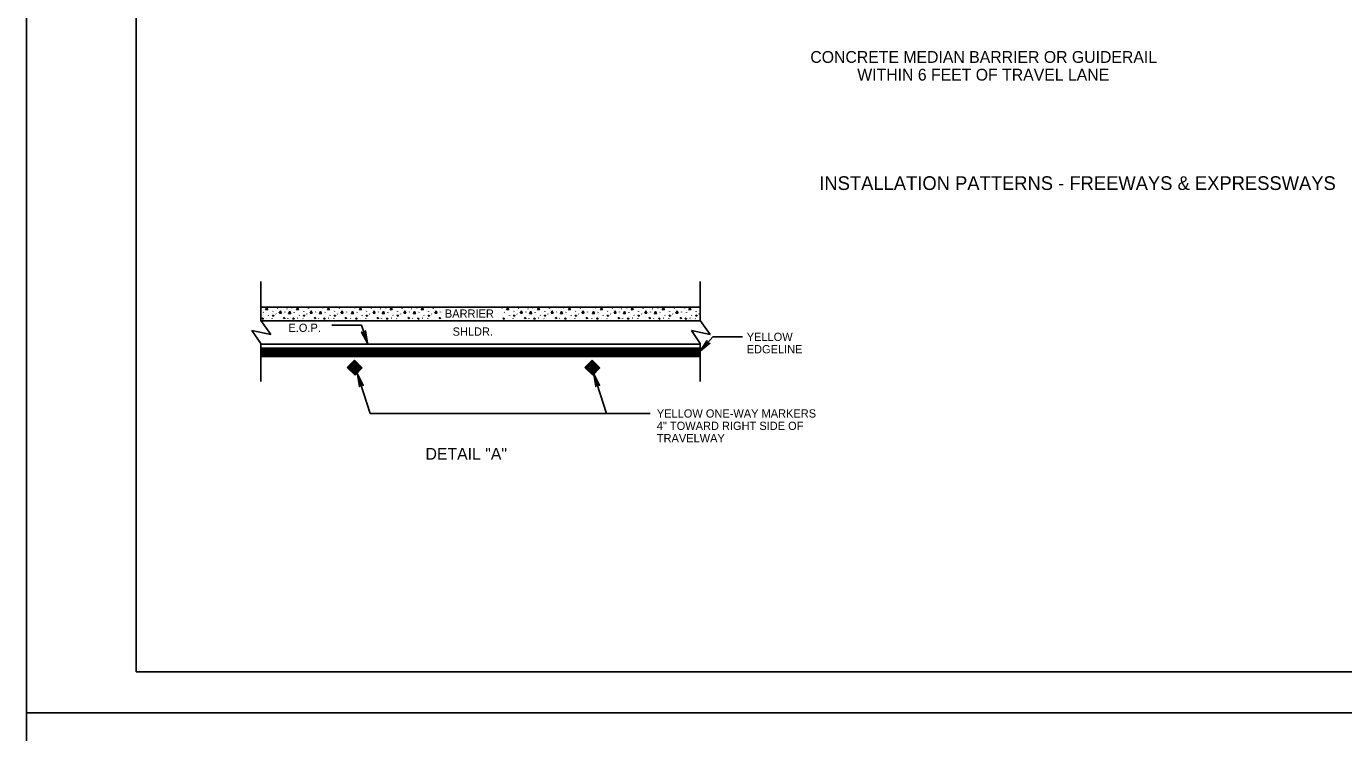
# Model space of a CAD drawing. Extents: x 639362 to 641108, y 298458 to 299646.
# Drawn here: x 639362.3 to 639841.8, y 299044.4 to 299301.7 of the extents above; entities that cross this region are included whole.
import ezdxf

# ---------------------------------------------------------------- set-up
doc = ezdxf.new("R2010")
doc.units = 0
for name, color, linetype in [('1', 7, 'Continuous'), ('2', 7, 'Continuous'), ('PLT-BNDY', 7, 'Continuous')]:
    doc.layers.add(name, color=color, linetype=linetype)

msp = doc.modelspace()

# ---------------------------------------------------------------- linework, layer by layer
at = {"layer": '1'}
for p, q in [((639402.31, 299630.63), (639402.31, 299066.63)), ((640188.31, 299066.63), (639402.31, 299066.63)), ((639402.31, 299066.63), (639988.31, 299066.63))]:
    msp.add_line(p, q, dxfattribs=at)
at = {"layer": '2'}
for p, q in [((639447.61, 299208.8), (639447.61, 299194.59)), ((639607.62, 299208.8), (639607.62, 299194.59)), ((639447.61, 299199.41), (639607.62, 299199.41)), ((639447.77, 299199.17), (639447.84, 299199.08)), ((639448.55, 299197.43), (639448.61, 299197.56)), ((639449.79, 299195.44), (639449.85, 299195.35)), ((639450.39, 299196.48), (639450.45, 299196.39)), ((639451.77, 299195.27), (639451.83, 299195.18)), ((639452.05, 299197.76), (639452.11, 299197.9)), ((639453.16, 299196.95), (639453.22, 299196.86)), ((639453.74, 299199.02), (639453.8, 299198.93)), ((639456.26, 299199.25), (639456.32, 299199.15)), ((639456.38, 299197.61), (639456.44, 299197.75)), ((639457.13, 299198.83), (639457.19, 299198.74)), ((639457.47, 299195.36), (639457.53, 299195.27)), ((639459, 299199.17), (639459.06, 299199.08)), ((639459.78, 299197.43), (639459.83, 299197.56)), ((639461.01, 299195.44), (639461.07, 299195.35)), ((639461.61, 299196.48), (639461.68, 299196.39)), ((639463, 299195.27), (639463.06, 299195.18)), ((639463.27, 299197.76), (639463.33, 299197.9)), ((639464.38, 299196.95), (639464.44, 299196.86)), ((639464.96, 299199.02), (639465.02, 299198.93)), ((639467.48, 299199.25), (639467.54, 299199.15)), ((639467.6, 299197.61), (639467.66, 299197.75)), ((639468.35, 299198.83), (639468.41, 299198.74)), ((639468.69, 299195.36), (639468.76, 299195.27)), ((639470.22, 299199.17), (639470.29, 299199.08)), ((639471, 299197.43), (639471.06, 299197.56)), ((639472.23, 299195.44), (639472.3, 299195.35)), ((639472.84, 299196.48), (639472.9, 299196.39)), ((639474.22, 299195.27), (639474.28, 299195.18)), ((639474.5, 299197.76), (639474.55, 299197.9)), ((639475.61, 299196.95), (639475.67, 299196.86)), ((639476.19, 299199.02), (639476.25, 299198.93)), ((639478.71, 299199.25), (639478.77, 299199.15)), ((639478.83, 299197.61), (639478.89, 299197.75)), ((639480.01, 299198.83), (639480.07, 299198.74)), ((639480.35, 299195.36), (639480.41, 299195.27)), ((639481.88, 299199.17), (639481.94, 299199.08)), ((639482.66, 299197.43), (639482.71, 299197.56)), ((639483.89, 299195.44), (639483.95, 299195.35)), ((639484.5, 299196.48), (639484.56, 299196.39)), ((639485.88, 299195.27), (639485.94, 299195.18)), ((639486.16, 299197.76), (639486.21, 299197.9)), ((639487.26, 299196.95), (639487.33, 299196.86)), ((639487.84, 299199.02), (639487.9, 299198.93)), ((639490.36, 299199.25), (639490.42, 299199.15)), ((639490.49, 299197.61), (639490.54, 299197.75)), ((639491.23, 299198.83), (639491.29, 299198.74)), ((639491.58, 299195.36), (639491.64, 299195.27)), ((639493.1, 299199.17), (639493.17, 299199.08)), ((639493.88, 299197.43), (639493.94, 299197.56)), ((639495.12, 299195.44), (639495.18, 299195.35)), ((639495.72, 299196.48), (639495.78, 299196.39)), ((639497.1, 299195.27), (639497.16, 299195.18)), ((639497.38, 299197.76), (639497.44, 299197.9)), ((639498.49, 299196.95), (639498.55, 299196.86)), ((639499.07, 299199.02), (639499.13, 299198.93)), ((639501.59, 299199.25), (639501.65, 299199.15)), ((639501.71, 299197.61), (639501.77, 299197.75)), ((639502.54, 299198.83), (639502.6, 299198.74)), ((639502.89, 299195.36), (639502.95, 299195.27)), ((639504.42, 299199.17), (639504.48, 299199.08)), ((639505.19, 299197.43), (639505.25, 299197.56)), ((639506.43, 299195.44), (639506.49, 299195.35)), ((639507.03, 299196.48), (639507.09, 299196.39)), ((639508.41, 299195.27), (639508.47, 299195.18)), ((639508.69, 299197.76), (639508.75, 299197.9)), ((639509.8, 299196.95), (639509.86, 299196.86)), ((639510.38, 299199.02), (639510.44, 299198.93)), ((639512.9, 299199.25), (639512.96, 299199.15)), ((639513.02, 299197.61), (639513.08, 299197.75)), ((639535.5, 299199.17), (639535.56, 299199.08)), ((639536.28, 299197.43), (639536.33, 299197.56)), ((639537.51, 299195.44), (639537.57, 299195.35)), ((639538.12, 299196.48), (639538.18, 299196.39)), ((639539.5, 299195.27), (639539.56, 299195.18)), ((639539.78, 299197.76), (639539.83, 299197.9)), ((639540.88, 299196.95), (639540.95, 299196.86)), ((639541.46, 299199.02), (639541.52, 299198.93)), ((639543.98, 299199.25), (639544.04, 299199.15)), ((639544.11, 299197.61), (639544.16, 299197.75)), ((639544.85, 299198.83), (639544.91, 299198.74)), ((639545.2, 299195.36), (639545.26, 299195.27)), ((639546.72, 299199.17), (639546.79, 299199.08)), ((639547.5, 299197.43), (639547.56, 299197.56)), ((639548.74, 299195.44), (639548.8, 299195.35)), ((639549.34, 299196.48), (639549.4, 299196.39)), ((639550.72, 299195.27), (639550.78, 299195.18)), ((639551, 299197.76), (639551.06, 299197.9)), ((639552.11, 299196.95), (639552.17, 299196.86)), ((639552.69, 299199.02), (639552.75, 299198.93)), ((639555.21, 299199.25), (639555.27, 299199.15)), ((639555.33, 299197.61), (639555.39, 299197.75)), ((639556.08, 299198.83), (639556.14, 299198.74)), ((639556.42, 299195.36), (639556.48, 299195.27)), ((639557.95, 299199.17), (639558.01, 299199.08)), ((639558.73, 299197.43), (639558.78, 299197.56)), ((639559.96, 299195.44), (639560.02, 299195.35)), ((639560.57, 299196.48), (639560.63, 299196.39)), ((639561.95, 299195.27), (639562.01, 299195.18)), ((639562.22, 299197.76), (639562.28, 299197.9)), ((639563.33, 299196.95), (639563.39, 299196.86)), ((639563.91, 299199.02), (639563.97, 299198.93)), ((639566.43, 299199.25), (639566.49, 299199.15)), ((639566.56, 299197.61), (639566.61, 299197.75)), ((639567.73, 299198.83), (639567.79, 299198.74)), ((639568.08, 299195.36), (639568.14, 299195.27)), ((639569.61, 299199.17), (639569.67, 299199.08)), ((639570.38, 299197.43), (639570.44, 299197.56)), ((639571.62, 299195.44), (639571.68, 299195.35)), ((639572.22, 299196.48), (639572.28, 299196.39)), ((639573.6, 299195.27), (639573.67, 299195.18)), ((639573.88, 299197.76), (639573.94, 299197.9)), ((639574.99, 299196.95), (639575.05, 299196.86)), ((639575.57, 299199.02), (639575.63, 299198.93)), ((639578.09, 299199.25), (639578.15, 299199.15)), ((639578.21, 299197.61), (639578.27, 299197.75)), ((639578.96, 299198.83), (639579.02, 299198.74)), ((639579.3, 299195.36), (639579.36, 299195.27)), ((639580.83, 299199.17), (639580.89, 299199.08)), ((639581.61, 299197.43), (639581.66, 299197.56)), ((639582.84, 299195.44), (639582.9, 299195.35)), ((639583.45, 299196.48), (639583.51, 299196.39)), ((639584.83, 299195.27), (639584.89, 299195.18)), ((639585.11, 299197.76), (639585.16, 299197.9)), ((639586.21, 299196.95), (639586.28, 299196.86)), ((639586.79, 299199.02), (639586.86, 299198.93)), ((639589.31, 299199.25), (639589.38, 299199.15)), ((639589.44, 299197.61), (639589.49, 299197.75)), ((639590.27, 299198.83), (639590.33, 299198.74)), ((639590.61, 299195.36), (639590.68, 299195.27)), ((639592.14, 299199.17), (639592.2, 299199.08)), ((639592.92, 299197.43), (639592.97, 299197.56)), ((639594.15, 299195.44), (639594.22, 299195.35)), ((639594.76, 299196.48), (639594.82, 299196.39)), ((639596.14, 299195.27), (639596.2, 299195.18)), ((639596.42, 299197.76), (639596.47, 299197.9)), ((639597.53, 299196.95), (639597.59, 299196.86)), ((639598.1, 299199.02), (639598.17, 299198.93)), ((639600.62, 299199.25), (639600.69, 299199.15)), ((639600.75, 299197.61), (639600.8, 299197.75)), ((639601.81, 299199.17), (639601.87, 299199.08)), ((639602.59, 299197.43), (639602.65, 299197.56)), ((639603.82, 299195.44), (639603.89, 299195.35)), ((639604.43, 299196.48), (639604.49, 299196.39)), ((639605.81, 299195.27), (639605.87, 299195.18)), ((639606.09, 299197.76), (639606.14, 299197.9)), ((639607.2, 299196.95), (639607.26, 299196.86)), ((639447.61, 299186.11), (639444.43, 299190.88)), ((639444.43, 299190.88), (639451.26, 299189.48)), ((639451.26, 299189.48), (639447.61, 299194.59)), ((639447.61, 299194.41), (639607.62, 299194.41)), ((639453.99, 299194.47), (639454.05, 299194.6)), ((639465.21, 299194.47), (639465.27, 299194.6)), ((639473.46, 299192.9), (639484.32, 299192.9)), ((639476.44, 299194.47), (639476.5, 299194.6)), ((639486.44, 299186.25), (639484.32, 299192.9)), ((639488.1, 299194.47), (639488.15, 299194.6)), ((639499.32, 299194.47), (639499.38, 299194.6)), ((639510.63, 299194.47), (639510.69, 299194.6)), ((639541.72, 299194.47), (639541.77, 299194.6)), ((639552.94, 299194.47), (639553, 299194.6)), ((639564.17, 299194.47), (639564.22, 299194.6)), ((639575.82, 299194.47), (639575.88, 299194.6)), ((639587.05, 299194.47), (639587.1, 299194.6)), ((639598.36, 299194.47), (639598.41, 299194.6)), ((639607.62, 299186.11), (639604.44, 299190.88)), ((639604.44, 299190.88), (639611.26, 299189.48)), ((639611.26, 299189.48), (639607.62, 299194.59)), ((639447.61, 299186.11), (639447.61, 299172.29)), ((639447.61, 299185.91), (639607.62, 299185.91)), ((639607.54, 299183.32), (639612.16, 299188.55)), ((639607.62, 299186.11), (639607.62, 299172.29)), ((639623.02, 299188.55), (639612.16, 299188.55)), ((639447.61, 299184.41), (639607.62, 299184.41)), ((639447.61, 299184.41), (639607.62, 299184.41)), ((639447.61, 299184.41), (639607.62, 299184.41)), ((639447.61, 299184.11), (639607.62, 299184.11)), ((639447.61, 299183.81), (639607.62, 299183.81)), ((639447.61, 299183.51), (639607.62, 299183.51)), ((639447.61, 299183.21), (639607.62, 299183.21)), ((639447.61, 299182.91), (639607.62, 299182.91)), ((639447.61, 299182.61), (639607.62, 299182.61)), ((639447.61, 299182.31), (639607.62, 299182.31)), ((639447.61, 299182.01), (639607.62, 299182.01)), ((639447.61, 299181.71), (639607.62, 299181.71)), ((639447.61, 299181.41), (639607.62, 299181.41)), ((639479.12, 299177.45), (639481.78, 299180.1)), ((639481.94, 299174.64), (639479.12, 299177.45)), ((639479.46, 299177.51), (639481.72, 299179.76)), ((639482, 299174.97), (639479.46, 299177.51)), ((639479.84, 299177.51), (639481.72, 299179.39)), ((639482, 299175.35), (639479.84, 299177.51)), ((639480.22, 299177.51), (639481.72, 299179.01)), ((639482, 299175.72), (639480.22, 299177.51)), ((639480.59, 299177.51), (639481.72, 299178.64)), ((639482, 299176.1), (639480.59, 299177.51)), ((639480.97, 299177.51), (639481.72, 299178.26)), ((639482, 299176.47), (639480.97, 299177.51)), ((639481.34, 299177.51), (639481.72, 299177.89)), ((639482, 299176.85), (639481.34, 299177.51)), ((639481.72, 299179.76), (639484.26, 299177.22)), ((639481.72, 299179.39), (639483.88, 299177.23)), ((639481.72, 299179.01), (639483.51, 299177.23)), ((639481.72, 299178.64), (639483.13, 299177.23)), ((639481.72, 299178.26), (639482.75, 299177.23)), ((639481.72, 299177.89), (639482.38, 299177.23)), ((639481.72, 299177.51), (639482, 299177.22)), ((639481.78, 299180.1), (639484.59, 299177.29)), ((639484.59, 299177.29), (639481.94, 299174.64)), ((639483.88, 299177.23), (639482, 299175.35)), ((639483.51, 299177.23), (639482, 299175.72)), ((639483.13, 299177.23), (639482, 299176.1)), ((639482.75, 299177.23), (639482, 299176.47)), ((639482.38, 299177.23), (639482, 299176.85)), ((639484.26, 299177.22), (639482, 299174.97)), ((639565.63, 299177.45), (639568.28, 299180.1)), ((639568.45, 299174.64), (639565.63, 299177.45)), ((639565.97, 299177.51), (639568.23, 299179.76)), ((639568.51, 299174.97), (639565.97, 299177.51)), ((639566.35, 299177.51), (639568.23, 299179.39)), ((639568.51, 299175.35), (639566.35, 299177.51)), ((639566.72, 299177.51), (639568.23, 299179.01)), ((639568.51, 299175.72), (639566.72, 299177.51)), ((639567.1, 299177.51), (639568.23, 299178.64)), ((639568.51, 299176.1), (639567.1, 299177.51)), ((639567.48, 299177.51), (639568.23, 299178.26)), ((639568.51, 299176.47), (639567.48, 299177.51)), ((639567.85, 299177.51), (639568.23, 299177.89)), ((639568.51, 299176.85), (639567.85, 299177.51)), ((639568.22, 299177.51), (639568.51, 299177.22)), ((639568.23, 299179.76), (639570.77, 299177.22)), ((639568.23, 299179.39), (639570.39, 299177.23)), ((639568.23, 299179.01), (639570.02, 299177.23)), ((639568.23, 299178.64), (639569.64, 299177.23)), ((639568.23, 299178.26), (639569.26, 299177.23)), ((639568.23, 299177.89), (639568.89, 299177.23)), ((639568.28, 299180.1), (639571.1, 299177.29)), ((639571.1, 299177.29), (639568.45, 299174.64)), ((639570.39, 299177.23), (639568.51, 299175.35)), ((639570.02, 299177.23), (639568.51, 299175.72)), ((639569.64, 299177.23), (639568.51, 299176.1)), ((639569.26, 299177.23), (639568.51, 299176.47)), ((639568.89, 299177.23), (639568.51, 299176.85)), ((639570.77, 299177.22), (639568.51, 299174.97)), ((639482.85, 299175.04), (639487.43, 299160.68)), ((639568.85, 299175.04), (639573.43, 299160.68)), ((639589.34, 299160.68), (639487.43, 299160.68))]:
    msp.add_line(p, q, dxfattribs=at)
msp.add_lwpolyline([(639447.61, 299194.41), (639607.62, 299194.41), (639607.62, 299199.41), (639447.61, 299199.41)], close=True, dxfattribs=at)
for points in [[(639448.11, 299195.04), (639448.28, 299195.41), (639448.58, 299195.19), (639448.11, 299195.04)], [(639449.42, 299198.44), (639449.82, 299199.19), (639450.13, 299198.5), (639449.43, 299198.44)], [(639451.94, 299196.1), (639452.12, 299196.46), (639452.41, 299196.25), (639451.94, 299196.1)], [(639454.38, 299197.22), (639454.78, 299197.97), (639455.1, 299197.27), (639454.4, 299197.22)], [(639455.94, 299195.23), (639456.12, 299195.6), (639456.41, 299195.38), (639455.94, 299195.23)], [(639457.78, 299197.03), (639458.18, 299197.78), (639458.49, 299197.09), (639457.79, 299197.03)], [(639459.33, 299195.04), (639459.51, 299195.41), (639459.8, 299195.19), (639459.33, 299195.04)], [(639460.64, 299198.44), (639461.04, 299199.19), (639461.35, 299198.5), (639460.66, 299198.44)], [(639463.17, 299196.1), (639463.35, 299196.46), (639463.64, 299196.25), (639463.17, 299196.1)], [(639465.61, 299197.22), (639466.01, 299197.97), (639466.32, 299197.27), (639465.62, 299197.22)], [(639467.17, 299195.23), (639467.34, 299195.6), (639467.64, 299195.38), (639467.17, 299195.23)], [(639469, 299197.03), (639469.4, 299197.78), (639469.71, 299197.09), (639469.01, 299197.03)], [(639470.56, 299195.04), (639470.73, 299195.41), (639471.03, 299195.19), (639470.56, 299195.04)], [(639471.87, 299198.44), (639472.27, 299199.19), (639472.57, 299198.5), (639471.88, 299198.44)], [(639474.39, 299196.1), (639474.57, 299196.46), (639474.86, 299196.25), (639474.39, 299196.1)], [(639476.83, 299197.22), (639477.23, 299197.97), (639477.55, 299197.27), (639476.85, 299197.22)], [(639478.39, 299195.23), (639478.57, 299195.6), (639478.86, 299195.38), (639478.39, 299195.23)], [(639480.66, 299197.03), (639481.06, 299197.78), (639481.37, 299197.09), (639480.67, 299197.03)], [(639482.21, 299195.04), (639482.39, 299195.41), (639482.68, 299195.19), (639482.21, 299195.04)], [(639483.52, 299198.44), (639483.92, 299199.19), (639484.23, 299198.5), (639483.54, 299198.44)], [(639486.05, 299196.1), (639486.23, 299196.46), (639486.52, 299196.25), (639486.05, 299196.1)], [(639488.49, 299197.22), (639488.89, 299197.97), (639489.2, 299197.27), (639488.51, 299197.22)], [(639490.05, 299195.23), (639490.22, 299195.6), (639490.52, 299195.38), (639490.05, 299195.23)], [(639491.88, 299197.03), (639492.28, 299197.78), (639492.59, 299197.09), (639491.9, 299197.03)], [(639493.44, 299195.04), (639493.61, 299195.41), (639493.91, 299195.19), (639493.44, 299195.04)], [(639494.75, 299198.44), (639495.15, 299199.19), (639495.46, 299198.5), (639494.76, 299198.44)], [(639497.27, 299196.1), (639497.45, 299196.46), (639497.75, 299196.25), (639497.27, 299196.1)], [(639499.71, 299197.22), (639500.11, 299197.97), (639500.43, 299197.27), (639499.73, 299197.22)], [(639501.27, 299195.23), (639501.45, 299195.6), (639501.74, 299195.38), (639501.27, 299195.23)], [(639503.2, 299197.03), (639503.59, 299197.78), (639503.9, 299197.09), (639503.21, 299197.03)], [(639504.75, 299195.04), (639504.92, 299195.41), (639505.22, 299195.19), (639504.75, 299195.04)], [(639506.06, 299198.44), (639506.46, 299199.19), (639506.77, 299198.5), (639506.08, 299198.44)], [(639508.58, 299196.1), (639508.76, 299196.46), (639509.06, 299196.25), (639508.58, 299196.1)], [(639511.03, 299197.22), (639511.42, 299197.97), (639511.74, 299197.27), (639511.04, 299197.22)], [(639512.58, 299195.23), (639512.76, 299195.6), (639513.06, 299195.38), (639512.58, 299195.23)], [(639535.83, 299195.04), (639536.01, 299195.41), (639536.3, 299195.19), (639535.83, 299195.04)], [(639537.14, 299198.44), (639537.54, 299199.19), (639537.85, 299198.5), (639537.16, 299198.44)], [(639539.67, 299196.1), (639539.85, 299196.46), (639540.14, 299196.25), (639539.67, 299196.1)], [(639542.11, 299197.22), (639542.51, 299197.97), (639542.82, 299197.27), (639542.13, 299197.22)], [(639543.67, 299195.23), (639543.84, 299195.6), (639544.14, 299195.38), (639543.67, 299195.23)], [(639545.5, 299197.03), (639545.9, 299197.78), (639546.21, 299197.09), (639545.52, 299197.03)], [(639547.06, 299195.04), (639547.23, 299195.41), (639547.53, 299195.19), (639547.06, 299195.04)], [(639548.37, 299198.44), (639548.77, 299199.19), (639549.08, 299198.5), (639548.38, 299198.44)], [(639550.89, 299196.1), (639551.07, 299196.46), (639551.37, 299196.25), (639550.89, 299196.1)], [(639553.33, 299197.22), (639553.73, 299197.97), (639554.05, 299197.27), (639553.35, 299197.22)], [(639554.89, 299195.23), (639555.07, 299195.6), (639555.36, 299195.38), (639554.89, 299195.23)], [(639556.73, 299197.03), (639557.13, 299197.78), (639557.44, 299197.09), (639556.74, 299197.03)], [(639558.28, 299195.04), (639558.46, 299195.41), (639558.75, 299195.19), (639558.28, 299195.04)], [(639559.59, 299198.44), (639559.99, 299199.19), (639560.3, 299198.5), (639559.61, 299198.44)], [(639562.12, 299196.1), (639562.3, 299196.46), (639562.59, 299196.25), (639562.12, 299196.1)], [(639564.56, 299197.22), (639564.96, 299197.97), (639565.27, 299197.27), (639564.58, 299197.22)], [(639566.12, 299195.23), (639566.29, 299195.6), (639566.59, 299195.38), (639566.12, 299195.23)], [(639568.39, 299197.03), (639568.78, 299197.78), (639569.09, 299197.09), (639568.4, 299197.03)], [(639569.94, 299195.04), (639570.11, 299195.41), (639570.41, 299195.19), (639569.94, 299195.04)], [(639571.25, 299198.44), (639571.65, 299199.19), (639571.96, 299198.5), (639571.27, 299198.44)], [(639573.77, 299196.1), (639573.95, 299196.46), (639574.25, 299196.25), (639573.77, 299196.1)], [(639576.22, 299197.22), (639576.61, 299197.97), (639576.93, 299197.27), (639576.23, 299197.22)], [(639577.77, 299195.23), (639577.95, 299195.6), (639578.25, 299195.38), (639577.77, 299195.23)], [(639579.61, 299197.03), (639580.01, 299197.78), (639580.32, 299197.09), (639579.62, 299197.03)], [(639581.16, 299195.04), (639581.34, 299195.41), (639581.64, 299195.19), (639581.16, 299195.04)], [(639582.47, 299198.44), (639582.87, 299199.19), (639583.18, 299198.5), (639582.49, 299198.44)], [(639585, 299196.1), (639585.18, 299196.46), (639585.47, 299196.25), (639585, 299196.1)], [(639587.44, 299197.22), (639587.84, 299197.97), (639588.15, 299197.27), (639587.46, 299197.22)], [(639589, 299195.23), (639589.17, 299195.6), (639589.47, 299195.38), (639589, 299195.23)], [(639590.92, 299197.03), (639591.32, 299197.78), (639591.63, 299197.09), (639590.93, 299197.03)], [(639592.47, 299195.04), (639592.65, 299195.41), (639592.95, 299195.19), (639592.47, 299195.04)], [(639593.78, 299198.44), (639594.18, 299199.19), (639594.49, 299198.5), (639593.8, 299198.44)], [(639596.31, 299196.1), (639596.49, 299196.46), (639596.78, 299196.25), (639596.31, 299196.1)], [(639598.75, 299197.22), (639599.15, 299197.97), (639599.47, 299197.27), (639598.77, 299197.22)], [(639600.31, 299195.23), (639600.48, 299195.6), (639600.78, 299195.38), (639600.31, 299195.23)], [(639602.14, 299195.04), (639602.32, 299195.41), (639602.62, 299195.19), (639602.14, 299195.04)], [(639603.46, 299198.44), (639603.85, 299199.19), (639604.16, 299198.5), (639603.47, 299198.44)], [(639605.98, 299196.1), (639606.16, 299196.46), (639606.45, 299196.25), (639605.98, 299196.1)], [(639485.62, 299190.53), (639485.37, 299190.28), (639486.44, 299186.25), (639485.62, 299190.53), (639485.73, 299190.8), (639486.44, 299186.25), (639484.96, 299190.14), (639484.62, 299190.19), (639486.44, 299186.25), (639484.35, 299190.35), (639484.62, 299190.19)], [(639610.02, 299186.9), (639610.14, 299186.58), (639607.54, 299183.32), (639610.02, 299186.9), (639610.02, 299187.19), (639607.54, 299183.32), (639610.46, 299186.28), (639610.8, 299186.19), (639607.54, 299183.32), (639611.1, 299186.23), (639610.8, 299186.19)], [(639483.67, 299170.76), (639483.92, 299171.01), (639482.85, 299175.04), (639483.67, 299170.76), (639483.56, 299170.5), (639482.85, 299175.04), (639484.33, 299171.16), (639484.67, 299171.1), (639482.85, 299175.04), (639484.94, 299170.95), (639484.67, 299171.1)], [(639569.67, 299170.76), (639569.92, 299171.01), (639568.85, 299175.04), (639569.67, 299170.76), (639569.56, 299170.5), (639568.85, 299175.04), (639570.33, 299171.16), (639570.67, 299171.1), (639568.85, 299175.04), (639570.94, 299170.95), (639570.67, 299171.1)]]:
    msp.add_lwpolyline(points, dxfattribs=at)
at = {"layer": 'PLT-BNDY'}
for points in [[(639362.31, 299645.63), (640203.31, 299645.63), (640203.31, 299051.63), (639362.31, 299051.63)], [(639362.31, 299051.63), (640203.31, 299051.63), (640203.31, 298457.63), (639362.31, 298457.63)]]:
    msp.add_lwpolyline(points, close=True, dxfattribs=at)

# ---------------------------------------------------------------- texts
at = {"layer": '2'}
for s, height, p in [('CONCRETE MEDIAN BARRIER OR GUIDERAIL', 4.3, (639647.67, 299288.38)), ('WITHIN 6 FEET OF TRAVEL LANE', 4.3, (639664.76, 299281.93)), ('INSTALLATION PATTERNS - FREEWAYS & EXPRESSWAYS', 5, (639650.93, 299242.08)), ('BARRIER', 3, (639514.65, 299195.56)), ('E.O.P.', 3, (639457.71, 299190.39)), ('SHLDR.', 3, (639517.47, 299189.01)), ('YELLOW ', 3, (639624.52, 299187.08)), ('EDGELINE', 3, (639624.52, 299182.58)), ('YELLOW ONE-WAY MARKERS', 3, (639591.8, 299159.18)), ('4" TOWARD RIGHT SIDE OF ', 3, (639591.8, 299154.68)), ('TRAVELWAY', 3, (639591.8, 299150.18)), ('DETAIL "A"', 4.3, (639507.61, 299143.84))]:
    msp.add_text(s, height=height, dxfattribs=at).set_placement(p)

doc.saveas('drawing.dxf')
